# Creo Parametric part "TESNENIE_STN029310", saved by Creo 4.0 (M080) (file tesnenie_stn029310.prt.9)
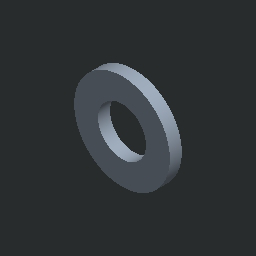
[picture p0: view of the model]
Units: millimeter Kilogram Sec (mmKs); MM, KILOGRAM, SECS
Materials in the file: POLYURETAN

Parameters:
  NAZOV = "TESNENIE_STN029310"
  NORMA = "STN 02 9310"
  NAZOV_1 = "START_PART_IPM"
  PTC_MATERIAL_NAME = "POLYURETAN"
  PRO_UNIT_SYS = "IPM (mmkgsecC)"

Other parameters: HMOTNOST, HUSTOTA, HMOTNOST_1, HUSTOTA_1

Layers: 1, 2, 3, 4, 5, 6, 7, 8, 9, 10, 11, 12, 13, 14, 15, 16, 17, 18, 19, 20, 21, 22, 23, 24, 25, 26, 27, 28, 29, 30, 31, 32

Family table entries: GENERIC, TESNENIE_4X8, TESNENIE_STN029310, value(d_val), 2/ , value(i_val), TESNENIE_5X9, TESNENIE_STN029310, 2/", TESNENIE_6X10, TESNENIE_STN029310, 2/$, TESNENIE_6X12, TESNENIE_STN029310, 2/(, TESNENIE_8X12, TESNENIE_STN029310, !/ , 2/(, TESNENIE_8X14, TESNENIE_STN029310, !/ , 2/,, TESNENIE_10X14, TESNENIE_STN029310, !/$, 2/,, TESNENIE_10X16, TESNENIE_STN029310, !/$, 2/0, TESNENIE_12X16, TESNENIE_STN029310, !/(, 2/0, TESNENIE_12X18, TESNENIE_STN029310, !/(, 2/2, TESNENIE_13X17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

Surfaces: 2 plane, 2 cylinder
